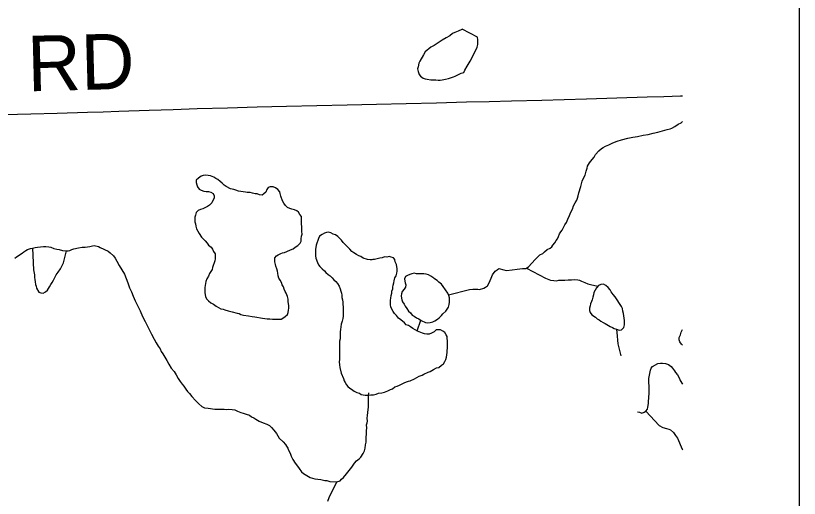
# Model space of a CAD drawing. Extents: x -11.4 to 84.1, y 11.1 to 59.
# Drawn here: x 32.362 to 33.165, y 46.252 to 46.747 of the extents above; entities that cross this region are included whole.
import ezdxf

# ---------------------------------------------------------------- set-up
doc = ezdxf.new("R2010")
doc.units = 0
for name, color, linetype in [('GM_X_Minor_Lake', 7, 'Continuous'), ('GM_X_Minor_River', 7, 'Continuous'), ('GM_X_Township_Road', 7, 'Continuous'), ('GM_X_Township_Road_Text', 7, 'Continuous'), ('SH_Data', 7, 'Continuous')]:
    doc.layers.add(name, color=color, linetype=linetype)

msp = doc.modelspace()

# ---------------------------------------------------------------- linework, layer by layer
at = {"layer": 'GM_X_Minor_Lake'}
for points in [[(32.81983, 46.73279), (32.81919, 46.73247), (32.81541, 46.73091), (32.812, 46.72935), (32.80974, 46.72819), (32.8071, 46.72588), (32.80332, 46.72395), (32.79917, 46.72162), (32.79087, 46.71622), (32.78747, 46.71428), (32.78182, 46.70967), (32.77996, 46.7066), (32.77623, 46.7001), (32.77512, 46.69781), (32.7744, 46.69438), (32.77404, 46.6921), (32.77445, 46.68944), (32.77563, 46.68641), (32.77679, 46.68452), (32.77985, 46.68265), (32.78176, 46.68191), (32.78367, 46.68155), (32.78748, 46.68082)], [(32.81983, 46.73279), (32.81919, 46.73247), (32.81541, 46.73091), (32.812, 46.72935), (32.80974, 46.72819), (32.8071, 46.72588), (32.80332, 46.72395), (32.79917, 46.72162), (32.79087, 46.71622), (32.78747, 46.71428), (32.78182, 46.70967), (32.77996, 46.7066), (32.77623, 46.7001), (32.77512, 46.69781), (32.7744, 46.69438), (32.77404, 46.6921), (32.77445, 46.68944), (32.77563, 46.68641), (32.77679, 46.68452), (32.77985, 46.68265), (32.78176, 46.68191), (32.78367, 46.68155), (32.78748, 46.68082), (32.7909, 46.68086), (32.7928, 46.68088), (32.79508, 46.68052), (32.79698, 46.68054), (32.79926, 46.68094), (32.80267, 46.68174), (32.80571, 46.68215), (32.80874, 46.68332), (32.81063, 46.6841), (32.81253, 46.6845), (32.81517, 46.68604), (32.81857, 46.6876), (32.82122, 46.68838), (32.82234, 46.69068), (32.82495, 46.69488), (32.82793, 46.69986), (32.83053, 46.70521), (32.83499, 46.71438), (32.83572, 46.71705), (32.83569, 46.71971), (32.83566, 46.72199), (32.83525, 46.72464), (32.81983, 46.73279)], [(32.78748, 46.68082), (32.7909, 46.68086), (32.7928, 46.68088), (32.79508, 46.68052), (32.79698, 46.68054), (32.79926, 46.68094), (32.80267, 46.68174), (32.80571, 46.68215), (32.80874, 46.68332), (32.81063, 46.6841), (32.81253, 46.6845), (32.81517, 46.68604), (32.81857, 46.6876), (32.82122, 46.68838), (32.82234, 46.69068), (32.82495, 46.69488), (32.82793, 46.69986), (32.83053, 46.70521), (32.83499, 46.71438), (32.83572, 46.71705), (32.83569, 46.71971), (32.83566, 46.72199), (32.83525, 46.72464), (32.81983, 46.73279)], [(32.61187, 46.56319), (32.6096, 46.56395), (32.60733, 46.56395), (32.60468, 46.56471), (32.60241, 46.56547), (32.59938, 46.56547), (32.59749, 46.56585), (32.59294, 46.56661), (32.59029, 46.56699), (32.58764, 46.56775), (32.58575, 46.56851), (32.58235, 46.56927), (32.5778, 46.57155), (32.57553, 46.57307), (32.57364, 46.57497), (32.57175, 46.57686), (32.56911, 46.57876), (32.56721, 46.5799), (32.56494, 46.58104), (32.56154, 46.58256), (32.55927, 46.58294), (32.55661, 46.58332), (32.55434, 46.58294), (32.55207, 46.58218), (32.54942, 46.58029), (32.54715, 46.57801), (32.54714, 46.57574), (32.54752, 46.57346), (32.54828, 46.57118), (32.55017, 46.56891), (32.55206, 46.56777), (32.55471, 46.56701), (32.55736, 46.56663), (32.55963, 46.56663), (32.5619, 46.56587), (32.56455, 46.56435), (32.5653, 46.56207), (32.5653, 46.5598), (32.56416, 46.55714), (32.56302, 46.55487), (32.56075, 46.55259), (32.55848, 46.55107), (32.55393, 46.5488), (32.55128, 46.54804), (32.54901, 46.54691), (32.54711, 46.54501), (32.54635, 46.54235), (32.54559, 46.54008), (32.54559, 46.53553), (32.54635, 46.53325), (32.54672, 46.53097), (32.54748, 46.52832), (32.54861, 46.52604), (32.55012, 46.52339), (32.55239, 46.51959), (32.55466, 46.51769), (32.55617, 46.5158), (32.55844, 46.51352), (32.55957, 46.51162), (32.56222, 46.50935), (32.56374, 46.50745), (32.56487, 46.50517), (32.56638, 46.50252), (32.56638, 46.49758), (32.56599, 46.49531), (32.56372, 46.48848), (32.56334, 46.48658), (32.5622, 46.48469), (32.56068, 46.48241), (32.55954, 46.47976), (32.55803, 46.4771), (32.55689, 46.47445), (32.55651, 46.47217)], [(32.63408, 46.43572), (32.63597, 46.43686), (32.63825, 46.43838), (32.64052, 46.44065), (32.64128, 46.44255), (32.64166, 46.44482), (32.64204, 46.4471), (32.64205, 46.44938), (32.64129, 46.45393), (32.64129, 46.4562), (32.64054, 46.45886), (32.63941, 46.46227), (32.63828, 46.46417), (32.63714, 46.46645), (32.63639, 46.46872), (32.63525, 46.471), (32.6345, 46.47328), (32.63299, 46.47555), (32.63185, 46.47783), (32.6311, 46.4801), (32.63072, 46.48276), (32.63034, 46.48504), (32.62959, 46.48731), (32.62883, 46.48997), (32.62846, 46.49187), (32.6277, 46.49452), (32.62771, 46.4987), (32.62922, 46.50059), (32.63112, 46.50173), (32.63377, 46.50287), (32.63566, 46.50362), (32.63756, 46.504), (32.63983, 46.50514), (32.64361, 46.50666), (32.64627, 46.50779), (32.64854, 46.50931), (32.65119, 46.5112), (32.65347, 46.51348), (32.6546, 46.51575), (32.65461, 46.51803), (32.65499, 46.52069), (32.65575, 46.52296), (32.65537, 46.52562), (32.65537, 46.53055), (32.655, 46.5332), (32.65501, 46.54079), (32.65311, 46.54307), (32.65198, 46.54534), (32.65009, 46.54686), (32.64782, 46.54762), (32.64517, 46.54838), (32.6429, 46.54914), (32.64063, 46.55028), (32.63874, 46.55218), (32.63685, 46.55445), (32.63534, 46.55711), (32.63383, 46.56167), (32.63307, 46.56432), (32.63269, 46.56622), (32.6308, 46.56849), (32.62815, 46.57039), (32.62588, 46.57115), (32.62286, 46.57115), (32.62096, 46.57077), (32.61944, 46.5685), (32.61831, 46.56584), (32.61641, 46.56395), (32.61452, 46.56281), (32.61187, 46.56319)], [(32.72708, 46.49638), (32.72538, 46.49638), (32.72273, 46.49676), (32.71819, 46.49828), (32.71592, 46.49979), (32.71365, 46.50056), (32.71138, 46.50207), (32.70873, 46.50359), (32.70646, 46.50511), (32.70457, 46.50739), (32.69776, 46.51422), (32.69587, 46.5165), (32.69436, 46.51839), (32.69209, 46.52029), (32.68982, 46.52219), (32.68755, 46.52295), (32.6849, 46.52409), (32.68263, 46.52485), (32.68073, 46.52447), (32.67846, 46.52371), (32.67619, 46.52257), (32.67354, 46.52068), (32.6724, 46.5184), (32.67012, 46.51157), (32.66936, 46.50702), (32.66936, 46.50475), (32.66935, 46.50057), (32.66973, 46.4983), (32.67124, 46.49374), (32.67237, 46.49147), (32.67389, 46.48957), (32.67615, 46.48729), (32.67842, 46.4854), (32.67994, 46.4835), (32.68221, 46.4816), (32.68448, 46.48008), (32.68637, 46.47818), (32.68826, 46.47591), (32.69015, 46.47439), (32.69204, 46.47211), (32.69355, 46.46946), (32.69469, 46.4668), (32.69544, 46.46452), (32.69582, 46.46225), (32.69619, 46.46035), (32.69619, 46.45808), (32.69695, 46.45542), (32.69732, 46.45314), (32.69732, 46.45087), (32.6977, 46.44821), (32.69769, 46.43873), (32.69731, 46.43645), (32.69655, 46.4338), (32.69579, 46.43076), (32.6954, 46.42773), (32.69502, 46.42507), (32.69464, 46.4228), (32.69464, 46.41559), (32.69388, 46.41331), (32.69387, 46.40307), (32.69386, 46.39966), (32.69386, 46.39435), (32.69348, 46.39207), (32.69385, 46.38904), (32.69423, 46.38638), (32.69574, 46.38031), (32.698, 46.375), (32.69876, 46.37272), (32.69989, 46.37082), (32.70103, 46.36855), (32.70254, 46.36665), (32.70443, 46.36513), (32.70632, 46.36399), (32.70897, 46.36209), (32.71162, 46.36058), (32.71427, 46.35982), (32.71616, 46.35868), (32.71805, 46.3583), (32.72033, 46.35792), (32.72335, 46.35792), (32.726, 46.3583), (32.72865, 46.35829), (32.73168, 46.35905)], [(32.80062, 46.39013), (32.80175, 46.3924), (32.80289, 46.3943), (32.80365, 46.39695), (32.80441, 46.40151), (32.80441, 46.40378), (32.80479, 46.40606), (32.8048, 46.40871), (32.8048, 46.41137), (32.8048, 46.41365), (32.80443, 46.41592), (32.80443, 46.41782), (32.80329, 46.41971), (32.80178, 46.42199), (32.79989, 46.42351), (32.79762, 46.42465), (32.79308, 46.42465), (32.7908, 46.42276), (32.78815, 46.42124), (32.78588, 46.42048), (32.78361, 46.42048), (32.78096, 46.42086), (32.77907, 46.42124), (32.77377, 46.42352), (32.7715, 46.42466), (32.76923, 46.42618), (32.76658, 46.4277), (32.76469, 46.42922), (32.76242, 46.42998), (32.76053, 46.43187), (32.75674, 46.43491), (32.75447, 46.43681), (32.7522, 46.43946), (32.75031, 46.44136), (32.7488, 46.44364), (32.74767, 46.44592), (32.74653, 46.44819), (32.74616, 46.45047), (32.74616, 46.45502), (32.74654, 46.45729), (32.74692, 46.45995), (32.74768, 46.46223), (32.74768, 46.4645), (32.74844, 46.46678), (32.74845, 46.46867), (32.74883, 46.47057), (32.74959, 46.47285), (32.74997, 46.47512), (32.75073, 46.47816), (32.75186, 46.48005), (32.75262, 46.48271), (32.753, 46.48499), (32.75301, 46.48726), (32.75225, 46.49181), (32.75112, 46.49447), (32.75075, 46.49674), (32.74923, 46.49864), (32.74696, 46.4994), (32.74469, 46.49978), (32.74242, 46.4994), (32.74015, 46.49941), (32.7375, 46.49865), (32.73522, 46.49827), (32.73257, 46.49751), (32.72992, 46.49676), (32.72803, 46.49676), (32.72708, 46.49638)], [(32.79048, 46.47757), (32.78972, 46.47852), (32.78745, 46.47966), (32.78518, 46.48118), (32.78291, 46.48194), (32.78026, 46.48232), (32.77269, 46.48232), (32.77042, 46.4827), (32.76815, 46.48232), (32.76587, 46.48156), (32.7636, 46.48043), (32.76171, 46.47929), (32.76057, 46.47702), (32.76094, 46.47474), (32.76132, 46.47284), (32.76208, 46.47095), (32.7617, 46.46867), (32.76018, 46.46639), (32.75829, 46.46412), (32.75753, 46.46184), (32.75715, 46.45957), (32.75752, 46.45729), (32.7579, 46.45539), (32.75865, 46.4535), (32.76017, 46.45122), (32.7613, 46.44894), (32.76281, 46.44667), (32.7647, 46.44401), (32.76659, 46.44211), (32.76848, 46.43984), (32.77038, 46.4387), (32.77302, 46.43718), (32.77529, 46.43604), (32.77756, 46.43452), (32.78211, 46.43224), (32.78438, 46.43186)], [(32.55651, 46.47217), (32.55613, 46.47027), (32.55575, 46.468), (32.55574, 46.46307), (32.55649, 46.45852), (32.55801, 46.45624), (32.55952, 46.45434), (32.56217, 46.45244), (32.56482, 46.45092), (32.56746, 46.44903), (32.56974, 46.44751), (32.57238, 46.44637), (32.57465, 46.44599), (32.57655, 46.44523), (32.57995, 46.44409), (32.58374, 46.44333), (32.58904, 46.44181), (32.59093, 46.44143), (32.59282, 46.44067), (32.59547, 46.43991), (32.60077, 46.43915), (32.60455, 46.43839), (32.60721, 46.43801), (32.61515, 46.43687), (32.6197, 46.43611), (32.62235, 46.4361), (32.62537, 46.43572), (32.63408, 46.43572)], [(32.78438, 46.43186), (32.78703, 46.43224), (32.78968, 46.433), (32.79157, 46.43414), (32.79422, 46.43565), (32.79612, 46.43717), (32.79839, 46.43945), (32.79991, 46.44134), (32.80294, 46.44399), (32.80445, 46.44589), (32.80559, 46.44817), (32.80635, 46.45082), (32.80673, 46.4531), (32.80674, 46.45765), (32.80598, 46.45993), (32.80485, 46.4622), (32.80031, 46.46903), (32.79842, 46.47169), (32.79577, 46.47359), (32.79388, 46.47549), (32.79123, 46.477), (32.79048, 46.47757)], [(32.983, 46.44869), (32.97634, 46.45871), (32.97445, 46.46099), (32.97256, 46.46365), (32.97143, 46.46592), (32.96916, 46.4682), (32.96689, 46.4701), (32.96462, 46.47162), (32.96197, 46.47124), (32.95932, 46.4701), (32.95742, 46.46783), (32.95591, 46.46555), (32.95477, 46.4629), (32.95439, 46.46062), (32.95363, 46.45834), (32.95287, 46.45569), (32.95211, 46.45379), (32.95135, 46.45152), (32.95097, 46.44924), (32.95021, 46.44697), (32.95021, 46.44469), (32.95096, 46.44241), (32.95247, 46.44014)], [(32.95247, 46.44014), (32.95626, 46.43786), (32.95815, 46.43596), (32.96004, 46.4352), (32.96193, 46.43368), (32.9642, 46.43217), (32.9661, 46.43141), (32.97139, 46.42837), (32.97366, 46.42723), (32.97556, 46.42609), (32.97783, 46.42533), (32.98047, 46.42457), (32.98313, 46.42495), (32.9854, 46.42723), (32.98616, 46.42988), (32.98616, 46.43443), (32.98541, 46.43899), (32.98504, 46.44164), (32.98428, 46.44392), (32.9839, 46.44657), (32.983, 46.44869)], [(33.0454, 46.40893), (33.04444, 46.41013), (33.04293, 46.41241), (33.04217, 46.41468), (33.04218, 46.41696), (33.04332, 46.41961), (33.04408, 46.42227), (33.04521, 46.42454), (33.0454, 46.42518)], [(32.73168, 46.35905), (32.73395, 46.35981), (32.73736, 46.36019), (32.74001, 46.36094), (32.74342, 46.36246), (32.74607, 46.3636), (32.74834, 46.36435), (32.75062, 46.36625), (32.75289, 46.36701), (32.75554, 46.36814), (32.76009, 46.37042), (32.76274, 46.37156), (32.76463, 46.37231), (32.76653, 46.37269), (32.77069, 46.37459), (32.77334, 46.3761), (32.77561, 46.37724), (32.77865, 46.37838), (32.78054, 46.37952), (32.78471, 46.38141), (32.78698, 46.38217), (32.79039, 46.38406), (32.79342, 46.38596), (32.79569, 46.38634), (32.79834, 46.38861), (32.80062, 46.39013)], [(32.99932, 46.34073), (33.00159, 46.34035), (33.00386, 46.33959), (33.00614, 46.34034), (33.00803, 46.34148), (33.00955, 46.34338), (33.00993, 46.34566), (33.01069, 46.34945), (33.01069, 46.3521), (33.01107, 46.35438), (33.01108, 46.35665), (33.01146, 46.35893), (33.01146, 46.36766), (33.01109, 46.37031), (33.01109, 46.37486), (33.01223, 46.38169), (33.01261, 46.38359), (33.01337, 46.38549), (33.01489, 46.38738), (33.02019, 46.39041), (33.02284, 46.39079), (33.02511, 46.39079), (33.02814, 46.39041), (33.03117, 46.38927), (33.03382, 46.38737), (33.03533, 46.38547), (33.03722, 46.38282), (33.03836, 46.38092), (33.04025, 46.37864), (33.04252, 46.37485), (33.04327, 46.37295), (33.0454, 46.36922)]]:
    msp.add_lwpolyline(points, dxfattribs=at)
at = {"layer": 'GM_X_Minor_River'}
for points in [[(32.80561, 46.46067), (32.82733, 46.46608), (32.83074, 46.46651), (32.83567, 46.46659), (32.83758, 46.46624), (32.84173, 46.46745), (32.84361, 46.46863), (32.84549, 46.4698), (32.84697, 46.4721), (32.84844, 46.47517), (32.84954, 46.47785), (32.85062, 46.48129), (32.8536, 46.48476), (32.85547, 46.48631), (32.85735, 46.48748), (32.86231, 46.48642), (32.86498, 46.48571), (32.87105, 46.48619), (32.87597, 46.48703), (32.88166, 46.4875), (32.88508, 46.48756), (32.88771, 46.4895), (32.89442, 46.49684), (32.89704, 46.49916), (32.89928, 46.50148), (32.90229, 46.50305), (32.90417, 46.5046), (32.90679, 46.50693), (32.9098, 46.5085), (32.91168, 46.50967), (32.91278, 46.51159), (32.91465, 46.5139), (32.91613, 46.51621), (32.91723, 46.51813), (32.91833, 46.52043), (32.91943, 46.52311), (32.92092, 46.52503), (32.92202, 46.52695), (32.9235, 46.52964), (32.92497, 46.53232), (32.92645, 46.53463), (32.92792, 46.53808), (32.92975, 46.54191), (32.93121, 46.54535), (32.93268, 46.54842), (32.93376, 46.55186), (32.93561, 46.55493), (32.93708, 46.55762), (32.93781, 46.55953), (32.93853, 46.56221), (32.93923, 46.56526), (32.93996, 46.56717), (32.94068, 46.56947), (32.9414, 46.57176), (32.94212, 46.57443), (32.94283, 46.57711), (32.94355, 46.5794), (32.94577, 46.58324), (32.94684, 46.58744), (32.94793, 46.5905), (32.94828, 46.59241), (32.95012, 46.59586), (32.9531, 46.59933), (32.95496, 46.60164), (32.95643, 46.60433), (32.95979, 46.60819), (32.96241, 46.61051), (32.96429, 46.61168), (32.96654, 46.61286), (32.96994, 46.61444), (32.97408, 46.61641), (32.97861, 46.618), (32.98315, 46.6196), (32.98958, 46.62123), (32.9945, 46.62207), (32.99942, 46.62291), (33.0051, 46.62414), (33.0104, 46.62499), (33.01532, 46.62621), (33.02024, 46.62743), (33.02516, 46.62865), (33.02969, 46.62987), (33.03272, 46.63068), (33.03461, 46.63147), (33.03762, 46.63304), (33.041, 46.63538), (33.04401, 46.63695), (33.0454, 46.63838)], [(32.36111, 46.49836), (32.36299, 46.49953), (32.36862, 46.50342), (32.3705, 46.5046), (32.37237, 46.50615), (32.37426, 46.50694), (32.37728, 46.50813), (32.37917, 46.50854), (32.38182, 46.50897), (32.38447, 46.50939), (32.3875, 46.50982), (32.39054, 46.51025), (32.39281, 46.51029), (32.39586, 46.50996), (32.39814, 46.50961), (32.40121, 46.50814), (32.40426, 46.50743), (32.40654, 46.50709), (32.40998, 46.50601), (32.41378, 46.50569), (32.41568, 46.50572), (32.41757, 46.50613), (32.41946, 46.50692), (32.42172, 46.50772), (32.42626, 46.50893), (32.43005, 46.50938), (32.43309, 46.50943), (32.43574, 46.50985), (32.43801, 46.51027), (32.44067, 46.51069), (32.44256, 46.5111), (32.44675, 46.51003), (32.44867, 46.5093), (32.45671, 46.50525), (32.45901, 46.50377), (32.4621, 46.50077), (32.46405, 46.49815), (32.46562, 46.49513)], [(32.37922, 46.50855), (32.3803, 46.48613), (32.38115, 46.4812), (32.38119, 46.47853), (32.38161, 46.47626), (32.38203, 46.47398), (32.38245, 46.47133), (32.38286, 46.46944), (32.38327, 46.46754), (32.38562, 46.4634), (32.38791, 46.46267), (32.3902, 46.46233), (32.39245, 46.46389), (32.3947, 46.46545), (32.39654, 46.4689), (32.39803, 46.4712), (32.39951, 46.47313), (32.40061, 46.47581), (32.40208, 46.4785), (32.40356, 46.48118), (32.40541, 46.48388), (32.40801, 46.48734), (32.40984, 46.49155), (32.41095, 46.49347), (32.41391, 46.50569)], [(32.46562, 46.49513), (32.46797, 46.4906), (32.47071, 46.48609), (32.47343, 46.48195), (32.47541, 46.47742), (32.477, 46.47288), (32.47861, 46.46796), (32.48057, 46.46381), (32.48255, 46.45928), (32.48453, 46.45437), (32.48728, 46.44909), (32.48964, 46.44419), (32.49201, 46.43852), (32.49476, 46.43324), (32.49829, 46.42646), (32.50105, 46.42042), (32.5038, 46.41514), (32.50614, 46.41138), (32.5081, 46.40799), (32.51004, 46.40535), (32.51122, 46.40271), (32.51279, 46.40008), (32.51474, 46.39669), (32.51708, 46.3933), (32.51904, 46.38953), (32.52139, 46.38539), (32.52448, 46.38202), (32.52644, 46.37862), (32.5284, 46.37485), (32.53073, 46.37185), (32.53268, 46.36922), (32.53423, 46.36696), (32.53656, 46.36396), (32.53812, 46.3617), (32.54006, 46.35945), (32.54239, 46.35645), (32.54625, 46.35233), (32.54973, 46.34897), (32.55281, 46.34635), (32.55549, 46.34488), (32.5593, 46.34456), (32.56615, 46.34353), (32.56805, 46.34356), (32.57223, 46.34363), (32.57565, 46.34369), (32.57793, 46.34334), (32.58059, 46.34339), (32.58401, 46.34306), (32.58668, 46.34273), (32.58935, 46.34163), (32.59279, 46.34017), (32.59509, 46.33944), (32.59815, 46.33835), (32.60158, 46.33727), (32.60388, 46.33578), (32.60618, 46.33468), (32.60811, 46.33319), (32.61156, 46.33135), (32.61576, 46.32952), (32.61959, 46.32806), (32.62226, 46.32696), (32.6242, 46.32471), (32.62652, 46.32209), (32.62924, 46.31871), (32.63198, 46.31381), (32.63622, 46.31008), (32.63854, 46.30745), (32.63972, 46.30557), (32.64089, 46.30369), (32.64168, 46.30142), (32.64325, 46.2984), (32.64444, 46.29538), (32.64602, 46.29199), (32.64836, 46.28822), (32.64991, 46.28634), (32.65263, 46.28259), (32.65497, 46.2792), (32.6569, 46.27771), (32.6638, 46.27364), (32.66876, 46.2722), (32.67485, 46.27154), (32.67904, 46.27047), (32.68094, 46.2705), (32.684, 46.26941), (32.69122, 46.26915), (32.69463, 46.26996), (32.69611, 46.27189), (32.69799, 46.27344), (32.70096, 46.27729), (32.70394, 46.28077), (32.70654, 46.28423), (32.70914, 46.28808), (32.71137, 46.29077), (32.714, 46.29272), (32.71587, 46.29427), (32.71809, 46.29811), (32.71956, 46.3008), (32.72027, 46.30347), (32.7206, 46.3069), (32.72131, 46.30957), (32.72126, 46.31261)], [(32.88568, 46.488), (32.905, 46.47762), (32.90691, 46.47689), (32.91035, 46.47581), (32.91377, 46.47548), (32.91643, 46.47514), (32.91871, 46.47556), (32.92136, 46.4756), (32.92478, 46.47566), (32.92819, 46.4761), (32.93161, 46.47615), (32.93503, 46.47621), (32.93807, 46.47588), (32.93998, 46.47553), (32.94189, 46.4748), (32.94533, 46.47334), (32.9484, 46.47186), (32.95107, 46.47115), (32.95107, 46.47115), (32.95874, 46.46941)], [(32.77357, 46.42362), (32.77724, 46.43474)], [(32.98262, 46.39828), (32.97949, 46.41061), (32.97856, 46.42199), (32.97819, 46.42523)], [(32.72126, 46.31261), (32.72122, 46.31489), (32.72155, 46.31794), (32.72149, 46.32136), (32.72182, 46.32441), (32.72177, 46.32745), (32.72212, 46.32936), (32.72247, 46.33126), (32.72242, 46.33431), (32.72275, 46.33697), (32.72308, 46.34002), (32.72341, 46.34307), (32.72375, 46.34574), (32.72371, 46.34763), (32.72368, 46.34992), (32.72363, 46.35258), (32.72359, 46.35524), (32.72355, 46.35752), (32.72389, 46.35981), (32.72389, 46.35981), (32.72388, 46.36019)], [(33.00803, 46.34148), (33.02147, 46.32666), (33.0253, 46.32482), (33.02912, 46.32374), (33.03141, 46.32302), (33.03332, 46.32229), (33.03641, 46.31968), (33.03836, 46.31667), (33.0403, 46.31366), (33.04504, 46.30271), (33.0454, 46.30171)], [(32.69122, 46.26915), (32.68423, 46.25573), (32.68314, 46.25267), (32.68169, 46.24884)]]:
    msp.add_lwpolyline(points, dxfattribs=at)
at = {"layer": 'GM_X_Township_Road'}
msp.add_lwpolyline([(32.35034, 46.64542), (32.37746, 46.64611), (32.40458, 46.6468), (32.43564, 46.64772), (32.45175, 46.6482), (32.46785, 46.64869), (32.4989, 46.64977), (32.52353, 46.65064), (32.54816, 46.6515), (32.57922, 46.65233), (32.60945, 46.65315), (32.63967, 46.65396), (32.67074, 46.65468), (32.7018, 46.6554), (32.73197, 46.6561), (32.76215, 46.6568), (32.79321, 46.6575), (32.82428, 46.65819), (32.84729, 46.65872), (32.8703, 46.65923), (32.90136, 46.66011), (32.92422, 46.66075), (32.94709, 46.66139), (32.97814, 46.66241), (33.00919, 46.66341), (33.02626, 46.66397), (33.04335, 46.66453), (33.0454, 46.66458)], dxfattribs=at)
at = {"layer": 'SH_Data'}
msp.add_line((33.16529, 47.54828), (33.16529, 40.54828), dxfattribs=at)

# ---------------------------------------------------------------- texts
at = {"layer": 'GM_X_Township_Road_Text'}
msp.add_text('RD', height=0.056818, rotation=1.48256, dxfattribs=at).set_placement((32.37462, 46.66905))

doc.saveas('drawing.dxf')
